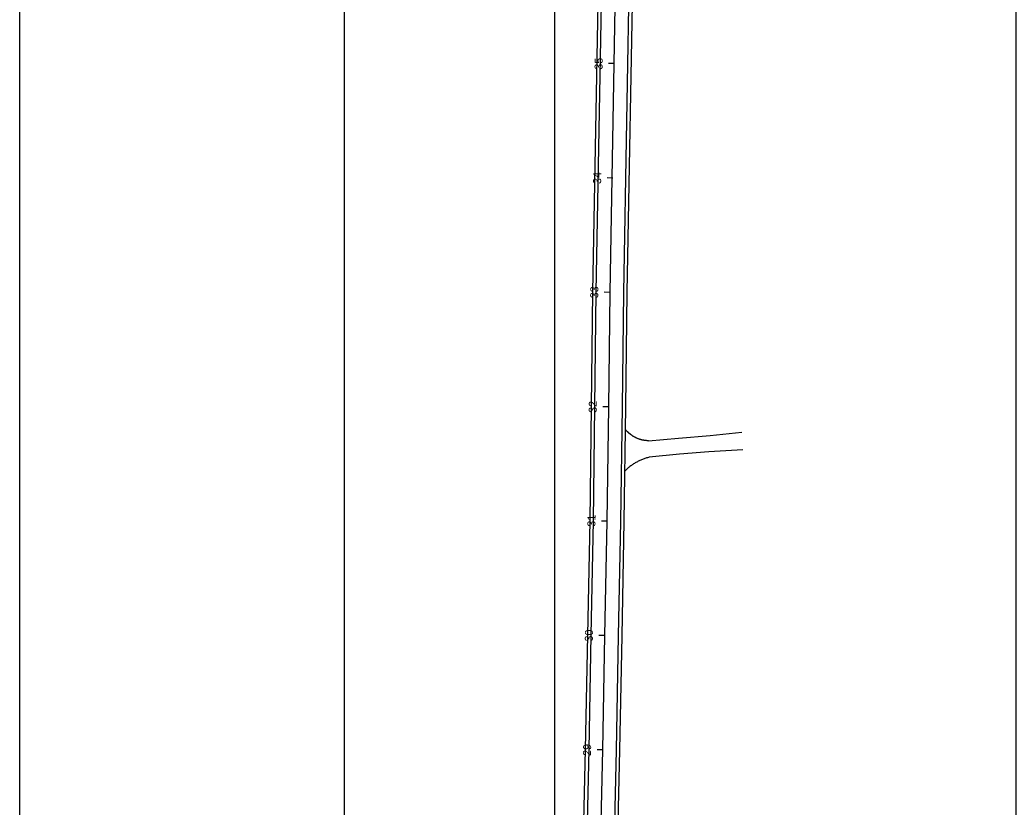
# Model space of a CAD drawing. Extents: x 2318076 to 2324211, y 613525 to 630327.
# Drawn here: x 2318413 to 2319284, y 617785 to 618473 of the extents above; entities that cross this region are included whole.
import ezdxf

# ---------------------------------------------------------------- set-up
doc = ezdxf.new("R2010")
doc.units = 0
for name, color, linetype in [('GE_P_CL_50', 7, 'Continuous'), ('PV_P_EOP', 7, 'Continuous'), ('PV_P_Shoulder', 7, 'Continuous'), ('PV_X_Driveway', 7, 'Continuous'), ('SC_Scratch3', 7, 'Continuous')]:
    doc.layers.add(name, color=color, linetype=linetype)

msp = doc.modelspace()

# ---------------------------------------------------------------- linework, layer by layer
at = {"layer": 'GE_P_CL_50'}
for p, q in [((2318932.61, 618435.05), (2318927.61, 618435.11)), ((2318931.36, 618335.06), (2318926.36, 618335.12)), ((2318928.83, 618235.09), (2318923.83, 618235.18)), ((2318927.51, 618135.1), (2318922.51, 618135.14)), ((2318926.34, 618035.11), (2318921.34, 618035.19)), ((2318924.12, 617935.14), (2318919.12, 617935.25)), ((2318922.5, 617835.15), (2318917.5, 617835.24))]:
    msp.add_line(p, q, dxfattribs=at)
msp.add_lwpolyline([(2318920.16, 617734.21), (2318922.5, 617835.15), (2318924.36, 617935.13), (2318926.34, 618035.11), (2318927.67, 618135.1), (2318928.83, 618235.09), (2318934.25, 618535.04)], dxfattribs=at)
at = {"layer": 'PV_P_EOP'}
for points in [[(2318908.16, 617734.48), (2318910.5, 617835.4), (2318912.36, 617935.36), (2318914.34, 618035.31), (2318915.67, 618135.25), (2318916.83, 618235.27), (2318922.25, 618535.27)], [(2318932.16, 617733.94), (2318934.5, 617834.9), (2318936.36, 617934.9), (2318938.34, 618034.91), (2318939.67, 618134.95), (2318940.83, 618234.92), (2318946.25, 618534.81)]]:
    msp.add_lwpolyline(points, dxfattribs=at)
at = {"layer": 'PV_P_Shoulder'}
for points in [[(2318905.16, 617734.55), (2318907.5, 617835.46), (2318909.36, 617935.42), (2318911.34, 618035.36), (2318912.67, 618135.29), (2318913.83, 618235.32), (2318919.25, 618535.32)], [(2318935.16, 617733.87), (2318937.5, 617834.84), (2318939.35, 617934.84), (2318941.34, 618034.86), (2318942.67, 618134.92), (2318943.83, 618234.87), (2318949.25, 618534.75)]]:
    msp.add_lwpolyline(points, dxfattribs=at)
at = {"layer": 'PV_X_Driveway'}
for points in [[(2318947.8, 618110.15), (2318947.68, 618110.24), (2318947.57, 618110.32), (2318947.45, 618110.41), (2318947.34, 618110.49), (2318947.23, 618110.58), (2318947.11, 618110.67), (2318947, 618110.76), (2318946.89, 618110.84), (2318946.77, 618110.93), (2318946.66, 618111.02), (2318946.55, 618111.11), (2318946.44, 618111.2), (2318946.32, 618111.29), (2318946.21, 618111.38), (2318946.1, 618111.47), (2318945.99, 618111.56), (2318945.88, 618111.66), (2318945.77, 618111.75), (2318945.66, 618111.84), (2318945.55, 618111.93), (2318945.44, 618112.03), (2318945.33, 618112.12), (2318945.23, 618112.21), (2318945.12, 618112.31), (2318945.01, 618112.4), (2318944.9, 618112.5), (2318944.8, 618112.6), (2318944.69, 618112.69), (2318944.58, 618112.79), (2318944.48, 618112.88), (2318944.37, 618112.98), (2318944.27, 618113.08), (2318944.16, 618113.18), (2318944.06, 618113.28), (2318943.95, 618113.37), (2318943.85, 618113.47), (2318943.75, 618113.57), (2318943.64, 618113.67), (2318943.54, 618113.77), (2318943.44, 618113.87), (2318943.34, 618113.98), (2318943.23, 618114.08), (2318943.13, 618114.18), (2318943.03, 618114.28), (2318942.93, 618114.38), (2318942.83, 618114.49), (2318942.73, 618114.59), (2318942.63, 618114.69), (2318942.4, 618114.93)], [(2318962.48, 618105.41), (2318988.75, 618107.73), (2319016.51, 618109.88), (2319044.18, 618112.92)], [(2318962.48, 618105.41), (2318962.06, 618105.41), (2318961.63, 618105.42), (2318961.21, 618105.44), (2318960.79, 618105.47), (2318960.37, 618105.5), (2318959.94, 618105.54), (2318959.52, 618105.58), (2318959.1, 618105.64), (2318958.68, 618105.7), (2318958.27, 618105.77), (2318957.85, 618105.84), (2318957.43, 618105.92), (2318957.02, 618106.01), (2318956.61, 618106.11), (2318956.2, 618106.21), (2318955.79, 618106.32), (2318955.38, 618106.44), (2318954.97, 618106.56), (2318954.57, 618106.69), (2318954.17, 618106.83), (2318953.77, 618106.97), (2318953.37, 618107.12), (2318952.98, 618107.28), (2318952.59, 618107.44), (2318952.2, 618107.61), (2318951.82, 618107.79), (2318951.43, 618107.97), (2318951.05, 618108.16), (2318950.68, 618108.36), (2318950.31, 618108.56), (2318949.94, 618108.77), (2318949.57, 618108.98), (2318949.21, 618109.21), (2318948.85, 618109.43), (2318948.5, 618109.67), (2318948.15, 618109.91), (2318947.8, 618110.15)], [(2319044.91, 618097.54), (2319015.14, 618095.82), (2318989.51, 618093.73), (2318963.1, 618090.91)], [(2318963.1, 618090.91), (2318962.34, 618090.72), (2318961.58, 618090.51), (2318960.83, 618090.3), (2318960.08, 618090.07), (2318959.34, 618089.82), (2318958.6, 618089.57), (2318957.86, 618089.3), (2318957.13, 618089.01), (2318956.41, 618088.72), (2318955.69, 618088.41), (2318954.97, 618088.09), (2318954.26, 618087.76), (2318953.56, 618087.42), (2318952.86, 618087.06), (2318952.17, 618086.69), (2318951.49, 618086.31), (2318950.81, 618085.92), (2318950.14, 618085.51), (2318949.47, 618085.1), (2318948.82, 618084.67), (2318948.17, 618084.23), (2318947.52, 618083.78), (2318946.89, 618083.32), (2318946.27, 618082.85), (2318945.65, 618082.37), (2318945.04, 618081.88), (2318944.44, 618081.37), (2318943.85, 618080.86), (2318943.27, 618080.34), (2318942.69, 618079.8), (2318941.93, 618079.06)]]:
    msp.add_lwpolyline(points, dxfattribs=at)
at = {"layer": 'SC_Scratch3'}
for p, q in [((2318412.82, 614778.41), (2318412.82, 630327.22)), ((2318696.66, 614778.41), (2318696.66, 630327.22)), ((2318880.45, 614778.41), (2318880.45, 630327.22)), ((2319283.9, 614778.41), (2319283.9, 630327.22))]:
    msp.add_line(p, q, dxfattribs=at)

# ---------------------------------------------------------------- texts
at = {"layer": 'GE_P_CL_50'}
for s, rotation, p in [('35', 89.26741, (2318922.29, 618429.71)), ('34', 89.28829, (2318921.04, 618329.8)), ('33', 89.01588, (2318918.48, 618229.89)), ('32', 89.57501, (2318917.21, 618129.77)), ('31', 89.07637, (2318916, 618030.19)), ('30', 88.66999, (2318913.74, 617929.8)), ('29', 88.92138, (2318912.15, 617829.84))]:
    msp.add_text(s, height=7, rotation=rotation, dxfattribs=at).set_placement(p)

doc.saveas('drawing.dxf')
